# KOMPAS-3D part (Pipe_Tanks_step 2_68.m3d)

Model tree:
1. X Axis
2. Y Axis
3. Z Axis  (labels: Pipe Dn 50; Valve Dy 50)
     Òîëùèíà ñòåíêè 1 = 1

Referenced files in C:\Documents and Settings\kashirsky\Мои документы\Camtasia Studio\Pipelines3D\Tanks\: Tanks_step 2.a3d
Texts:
  Pipe Dn 50
  Steel ASTM A295
  Three Point Plane
  Plane at Angle
  Line and Point Plane
  Axis through Two Vertices
  Axis of Feature
  Axis of Conical Surface
  Axis through Edge
  Trim by Surface
  Trim by Sketch
  Feature with No History
  Intersection Axis of Two Planes
  Two Line Plane
  Line and Face Plane
  Bend by line
  Hole in sheet body
  Cut in sheet body
  Point in CM
  Linear Dimension from Line to Point
  Surface Finish Symbol
  Geometric Tolerance Symbol
  Leader #1
  Leader #2
  Leader #3
  Shape Deviations and Datum
  Node point number
  Mark of coordination axis
  Node point designation
  Mark/Reference designation with leader
  Mark/reference designation on line
  Mark/Reference designation without leader
  Valve Dy 50
  Plane of section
